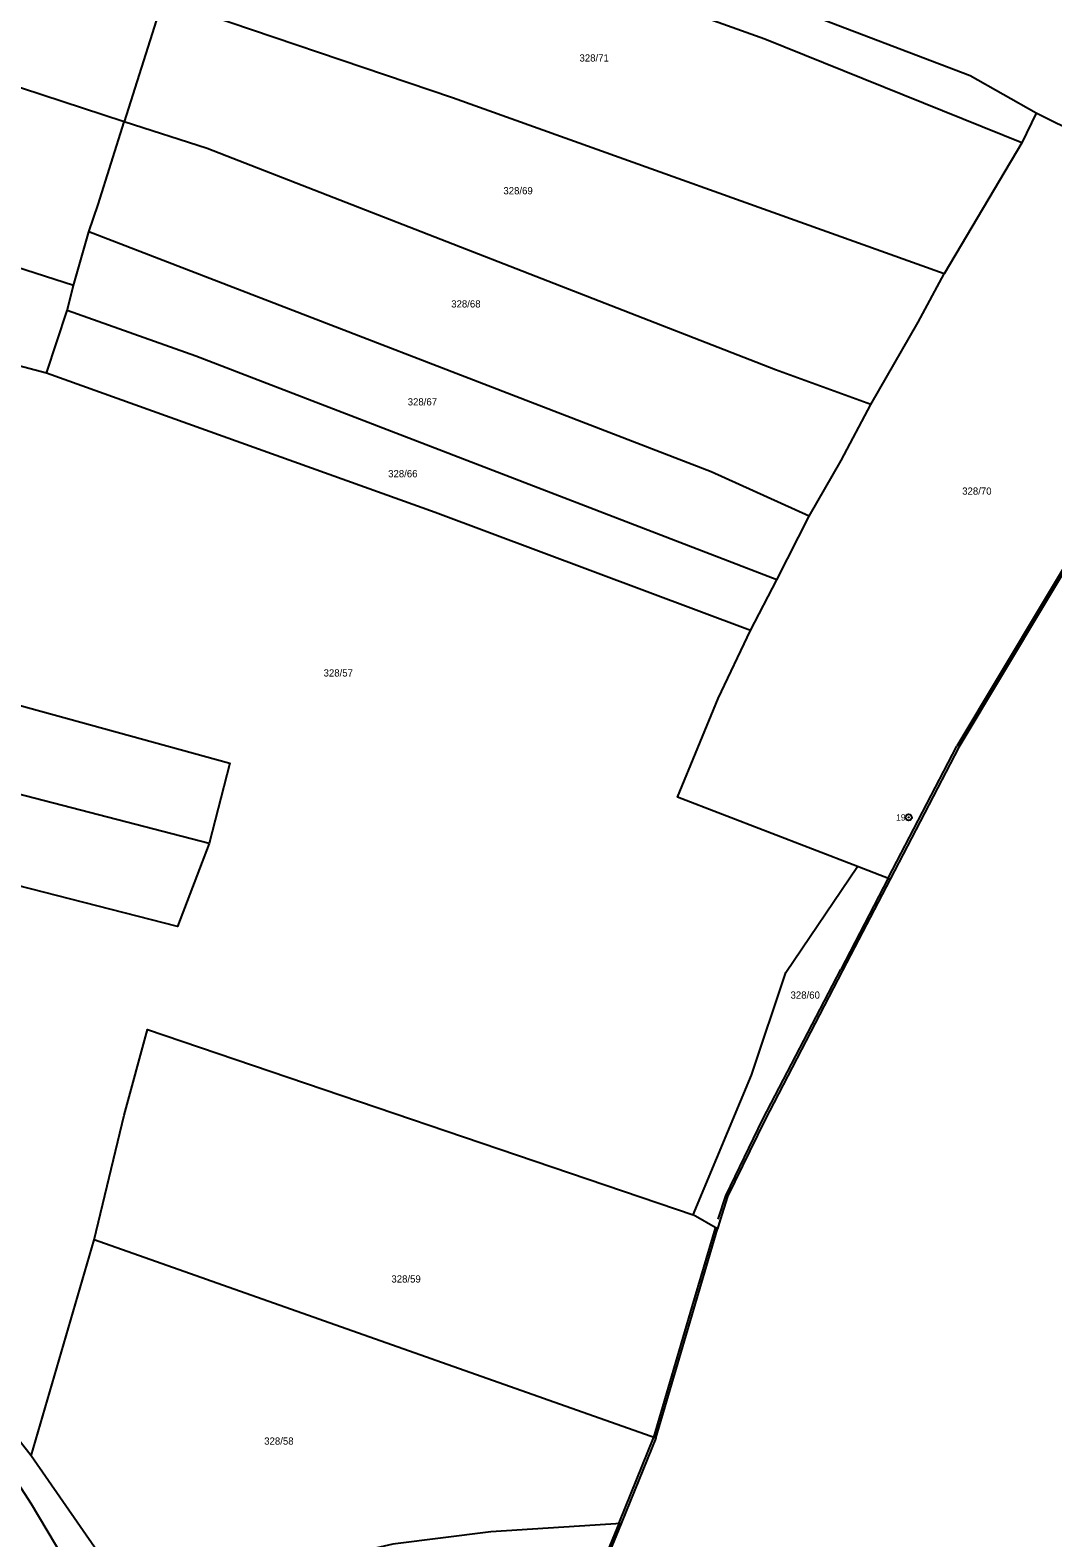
# Model space of a CAD drawing. Extents: x -783948 to -781889, y -1005870 to -1004430.
# Drawn here: x -782402.5 to -782160.3, y -1005350.5 to -1004993.6 of the extents above; entities that cross this region are included whole.
import ezdxf

# ---------------------------------------------------------------- set-up
doc = ezdxf.new("R2010")
doc.units = 0
for name, color, linetype in [('Vrstva 1', 7, 'Continuous'), ('Vrstva 2', 7, 'Continuous'), ('Vrstva 4', 7, 'Continuous'), ('Vrstva 6', 7, 'Continuous'), ('Vrstva 8', 7, 'Continuous')]:
    doc.layers.add(name, color=color, linetype=linetype)

msp = doc.modelspace()

# ---------------------------------------------------------------- linework, layer by layer
at = {"layer": 'Vrstva 1'}
for p, q in [((-782371.08, -1004986.39), (-782380.26, -1005015.34)), ((-782164.3, -1005013.28), (-782167.64, -1005020.28)), ((-782167.64, -1005020.28), (-782186.06, -1005051.26)), ((-782392.2, -1005054.05), (-782388.61, -1005041.33)), ((-782398.61, -1005074.84), (-782483.01, -1005052.11)), ((-782393.71, -1005059.95), (-782392.2, -1005054.05)), ((-782398.61, -1005074.84), (-782393.71, -1005059.95)), ((-782225.7, -1005123.71), (-782217.98, -1005108.68)), ((-782231.92, -1005135.69), (-782225.7, -1005123.71)), ((-782198.84, -1005194.53), (-782206.58, -1005191.54)), ((-782239.75, -1005277.29), (-782245.52, -1005274.01)), ((-782402.29, -1005331.02), (-782387.37, -1005279.96)), ((-782254.33, -1005326.85), (-782387.37, -1005279.96)), ((-782254.33, -1005326.85), (-782239.75, -1005277.29)), ((-782254.33, -1005326.85), (-782262.57, -1005347.08)), ((-782378.99, -1005364.51), (-782402.29, -1005331.02)), ((-782262.57, -1005347.08), (-782265.3, -1005353.79))]:
    msp.add_line(p, q, dxfattribs=at)
for points in [[(-782164.3, -1005013.28), (-782179.86, -1005004.46), (-782263.73, -1004972.51), (-782246.02, -1004931.17), (-782268.59, -1004924.1), (-782332.13, -1004903.18), (-782369.47, -1004892.92)], [(-782380.26, -1005015.34), (-782506.21, -1004974.01), (-782572.86, -1004951.65)], [(-782167.64, -1005020.28), (-782228.54, -1004995.74), (-782268.06, -1004981.53), (-782360.79, -1004952.21), (-782371.08, -1004986.39)], [(-782186.06, -1005051.26), (-782302.45, -1005009.61), (-782371.08, -1004986.39)], [(-782392.2, -1005054.05), (-782435.01, -1005040.31), (-782548.29, -1005005.8), (-782584.34, -1004995.55)], [(-782388.61, -1005041.33), (-782386.43, -1005034.91), (-782380.26, -1005015.34)], [(-782203.4, -1005082.23), (-782225.97, -1005073.98), (-782360.57, -1005021.63), (-782380.26, -1005015.34)], [(-782108.03, -1005044.7), (-782133.48, -1005029.07), (-782143.11, -1005023.77), (-782164.3, -1005013.28)], [(-782217.98, -1005108.68), (-782241.26, -1005098.16), (-782388.61, -1005041.33)], [(-782203.4, -1005082.23), (-782192.21, -1005062.72), (-782186.06, -1005051.26)], [(-782225.7, -1005123.71), (-782363.24, -1005070.78), (-782393.71, -1005059.95)], [(-782231.92, -1005135.69), (-782306.59, -1005107.78), (-782398.61, -1005074.84)], [(-782131.43, -1005075.34), (-782151.82, -1005111.96), (-782182.59, -1005163.31), (-782198.84, -1005194.53)], [(-782217.98, -1005108.68), (-782210.44, -1005095.49), (-782203.4, -1005082.23)], [(-782498.13, -1005129.54), (-782408.58, -1005152.47), (-782355.25, -1005167.12), (-782360.07, -1005186.14)], [(-782206.58, -1005191.54), (-782249.17, -1005175.12), (-782239.55, -1005151.78), (-782231.92, -1005135.69)], [(-782360.07, -1005186.14), (-782418.96, -1005170.89), (-782502.18, -1005148.24)], [(-782360.07, -1005186.14), (-782367.58, -1005205.75), (-782449.91, -1005184.73), (-782506.17, -1005169.11)], [(-782245.52, -1005274.01), (-782231.64, -1005240.94), (-782223.54, -1005216.67), (-782206.58, -1005191.54)], [(-782198.84, -1005194.53), (-782210.11, -1005216.18), (-782228.54, -1005251.6), (-782237.32, -1005269.7)], [(-782402.29, -1005331.02), (-782436.69, -1005287.11), (-782455.38, -1005266.01), (-782514.05, -1005216.76)], [(-782387.37, -1005279.96), (-782380.26, -1005250.41), (-782374.7, -1005230.15), (-782245.52, -1005274.01)], [(-782237.32, -1005269.7), (-782239.13, -1005275.17), (-782239.75, -1005277.29)], [(-782262.57, -1005347.08), (-782293.38, -1005349), (-782316.62, -1005351.98), (-782365.34, -1005363.17), (-782378.99, -1005364.51)]]:
    msp.add_lwpolyline(points, dxfattribs=at)
at = {"layer": 'Vrstva 4'}
for p, q in [((-782152.25, -1005111.7), (-782183.02, -1005163.05)), ((-782199.28, -1005194.3), (-782183.03, -1005163.08)), ((-782199.28, -1005194.3), (-782210.55, -1005215.95)), ((-782228.98, -1005251.37), (-782210.55, -1005215.95)), ((-782237.77, -1005269.48), (-782228.99, -1005251.38)), ((-782239.6, -1005275.01), (-782237.79, -1005269.54)), ((-782245.71, -1005295.76), (-782240.23, -1005277.15)), ((-782254.81, -1005326.71), (-782245.71, -1005295.76)), ((-782263.03, -1005346.89), (-782254.79, -1005326.66)), ((-782263.03, -1005346.89), (-782265.76, -1005353.6))]:
    msp.add_line(p, q, dxfattribs=at)
at = {"layer": 'Vrstva 6'}
for p, q in [((-782409.41, -1005331.25), (-782402.26, -1005342.4)), ((-782402.26, -1005342.4), (-782386.33, -1005369.12))]:
    msp.add_line(p, q, dxfattribs=at)
at = {"layer": 'Vrstva 8'}
for radius in [0.75, 0.03]:
    msp.add_circle((-782194.46, -1005179.94), radius, dxfattribs=at)

# ---------------------------------------------------------------- texts
at = {"layer": 'Vrstva 2'}
for s, p in [('328/71', (-782272.41, -1005001.05)), ('328/69', (-782290.43, -1005032.47)), ('328/68', (-782302.79, -1005059.26)), ('328/67', (-782313.09, -1005082.44)), ('328/66', (-782317.72, -1005099.44)), ('328/70', (-782181.78, -1005103.56)), ('328/57', (-782333.01, -1005146.6)), ('328/60', (-782222.43, -1005222.84)), ('328/59', (-782316.95, -1005290.03)), ('328/58', (-782347.07, -1005328.4))]:
    msp.add_text(s, height=1.7, dxfattribs=at).set_placement(p)
at = {"layer": 'Vrstva 8'}
msp.add_text('19', height=1.5, dxfattribs=at).set_placement((-782197.42, -1005180.69))

doc.saveas('drawing.dxf')
